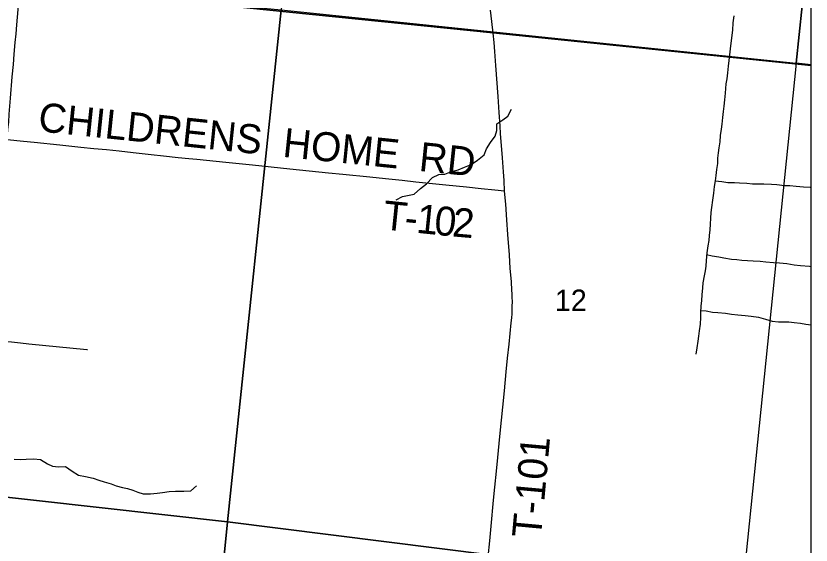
# Model space of a CAD drawing. Extents: x 0 to 1067, y 0 to 440.
# Drawn here: x 803.284 to 804.84, y 352.266 to 353.302 of the extents above; entities that cross this region are included whole.
import ezdxf

# ---------------------------------------------------------------- set-up
doc = ezdxf.new("R2010")
doc.units = 0
for name, color, linetype in [('GM_X_City_Street', 7, 'Continuous'), ('GM_X_Minor_River', 7, 'Continuous'), ('GM_X_Section', 7, 'Continuous'), ('GM_X_Section_Text', 7, 'Continuous'), ('GM_X_Township_Road', 7, 'Continuous'), ('GM_X_Township_Road_Text', 7, 'Continuous'), ('GM_X_US_Shield', 7, 'Continuous')]:
    doc.layers.add(name, color=color, linetype=linetype)

msp = doc.modelspace()

# ---------------------------------------------------------------- linework, layer by layer
at = {"layer": 'GM_X_City_Street'}
msp.add_lwpolyline([(803.254, 352.6093), (803.2546, 352.6163), (803.2565, 352.6361), (803.2583, 352.6522), (803.2589, 352.659), (803.2593, 352.6608), (803.2598, 352.6619), (803.2605, 352.6629), (803.2615, 352.6637), (803.2632, 352.6645), (803.265, 352.6647), (803.2755, 352.6637), (803.2935, 352.6618), (803.3095, 352.6601), (803.4231, 352.6488), (803.4243, 352.6487)], dxfattribs=at)
at = {"layer": 'GM_X_Minor_River'}
for points in [[(804.689, 353.302), (804.687, 353.2884), (804.6865, 353.274), (804.6853, 353.2641), (804.6837, 353.2528), (804.6825, 353.2433), (804.6812, 353.2316), (804.678, 353.2035), (804.6767, 353.1907), (804.6751, 353.1789), (804.6735, 353.1691), (804.6719, 353.1509), (804.6706, 353.1376), (804.6694, 353.1251), (804.6682, 353.1149), (804.6669, 353.1031), (804.6653, 353.0899), (804.6641, 353.08), (804.6621, 353.0675), (804.6613, 353.0554), (804.6596, 353.0437), (804.6584, 353.0342), (804.6572, 353.0236), (804.6567, 353.013), (804.6551, 353.0012), (804.6539, 352.9895), (804.6523, 352.9793), (804.6507, 352.9683), (804.6491, 352.9547), (804.6471, 352.9414), (804.6451, 352.927), (804.6442, 352.9172), (804.6434, 352.9062), (804.6425, 352.894), (804.6417, 352.8834), (804.6405, 352.8721), (804.64, 352.8626), (804.6384, 352.852), (804.636, 352.8384), (804.6348, 352.8232), (804.6343, 352.8122), (804.6331, 352.8027), (804.6311, 352.7929), (804.6283, 352.7797), (804.6275, 352.7694), (804.6266, 352.7558), (804.6254, 352.7448), (804.6246, 352.7338), (804.6237, 352.7213), (804.6236, 352.7114), (804.6231, 352.6986), (804.6211, 352.6857), (804.6199, 352.6754), (804.6183, 352.6656), (804.6167, 352.6523), (804.6147, 352.6399)], [(804.0281, 352.9422), (804.0407, 352.9486), (804.0536, 352.9511), (804.0634, 352.953), (804.0756, 352.9639), (804.0878, 352.9732), (804.0992, 352.9857), (804.1118, 352.9916), (804.1235, 352.9923), (804.1364, 352.9975), (804.1493, 353.0008), (804.1622, 353.006), (804.1747, 353.0112), (804.1873, 353.0198), (804.2002, 353.03), (804.2053, 353.0417), (804.2126, 353.0541), (804.2217, 353.0662), (804.2249, 353.0779), (804.225, 353.0908), (804.2368, 353.0987), (804.247, 353.1058), (804.2536, 353.1194)], [(804.6523, 352.9792), (804.6652, 352.9777), (804.6773, 352.976), (804.6905, 352.9756), (804.7003, 352.9751), (804.7147, 352.9746), (804.7253, 352.9734), (804.7476, 352.9732), (804.7627, 352.9727), (804.7733, 352.9718), (804.7884, 352.9702), (804.7983, 352.9697), (804.8111, 352.9685), (804.8255, 352.9676), (804.838, 352.9664), (804.8401, 352.966)], [(804.6357, 352.8347), (804.6466, 352.8326), (804.6594, 352.8306), (804.6692, 352.8286), (804.6843, 352.8258), (804.6949, 352.825), (804.7047, 352.8238), (804.7157, 352.8233), (804.7271, 352.8224), (804.7407, 352.8216), (804.7516, 352.8203), (804.7668, 352.8195), (804.7781, 352.8186), (804.7928, 352.8173), (804.8072, 352.8149), (804.8197, 352.8137), (804.8367, 352.812), (804.8401, 352.8113)], [(804.624, 352.7252), (804.6351, 352.7246), (804.6472, 352.7222), (804.6578, 352.7214), (804.6729, 352.7198), (804.6842, 352.7181), (804.6967, 352.7169), (804.7114, 352.7153), (804.7231, 352.714), (804.7371, 352.7124), (804.7507, 352.7081), (804.7639, 352.7046), (804.7764, 352.7033), (804.7866, 352.7029), (804.7964, 352.7032), (804.807, 352.7016), (804.8195, 352.7003), (804.8297, 352.6987), (804.8401, 352.6974)], [(803.2805, 352.4344), (803.2938, 352.4339), (803.304, 352.4346), (803.3184, 352.4348), (803.3324, 352.4336), (803.3459, 352.4255), (803.3557, 352.4209), (803.3674, 352.4193), (803.3811, 352.4199), (803.3942, 352.4111), (803.4066, 352.4031), (803.4206, 352.4003), (803.4353, 352.3971)], [(803.4353, 352.3971), (803.4463, 352.3933), (803.4568, 352.3898), (803.4708, 352.3859), (803.4806, 352.382), (803.4927, 352.3789), (803.5025, 352.3769), (803.5127, 352.3734), (803.5225, 352.3699), (803.5331, 352.3664), (803.5478, 352.3663), (803.5607, 352.3677), (803.5709, 352.3692), (803.5838, 352.3709), (803.5967, 352.372), (803.6129, 352.3715), (803.6266, 352.3721), (803.6376, 352.3819)]]:
    msp.add_lwpolyline(points, dxfattribs=at)
at = {"layer": 'GM_X_Section'}
for points in [[(803.8031, 353.3139), (803.6983, 352.312), (802.6931, 352.4236), (802.7829, 353.4125)], [(804.8106, 353.2091), (804.7094, 352.2121), (804.2114, 352.247), (803.6983, 352.312), (803.8031, 353.3139)], [(802.6931, 352.4236), (803.6983, 352.312), (803.5984, 351.3051), (802.5998, 351.3996)], [(803.6983, 352.312), (804.2114, 352.247), (804.7094, 352.2121), (804.6132, 351.2048), (803.5984, 351.3051)]]:
    msp.add_lwpolyline(points, close=True, dxfattribs=at)
at = {"layer": 'GM_X_Township_Road'}
for points in [[(803.2927, 353.3636), (804.2178, 353.2689), (804.8401, 353.205), (804.8401, 357.6021)], [(799.4572, 350.8021), (804.8401, 350.8021), (804.8401, 353.205), (804.2178, 353.2689), (803.2927, 353.3636)], [(803.2844, 353.2671), (803.2858, 353.2842), (803.2886, 353.3145), (803.2918, 353.3491), (803.293, 353.3631)], [(804.218, 353.2684), (804.2157, 353.2907), (804.2131, 353.3129)], [(803.2669, 353.0592), (803.2687, 353.0793), (803.2701, 353.0942), (803.2713, 353.1096), (803.2738, 353.1412), (803.2772, 353.1827), (803.2793, 353.2068), (803.2811, 353.2272), (803.283, 353.2501), (803.2844, 353.2671)], [(804.2404, 352.959), (804.2396, 352.9798), (804.2384, 352.9965), (804.2363, 353.0238), (804.2338, 353.056), (804.2327, 353.0708), (804.2316, 353.087), (804.23, 353.113), (804.2278, 353.144), (804.2235, 353.2047), (804.2215, 353.232), (804.2199, 353.2499), (804.218, 353.2684)], [(803.4864, 353.0373), (803.4617, 353.0396), (803.4364, 353.042), (803.4111, 353.0446), (803.3704, 353.0488), (803.3198, 353.0538), (803.2988, 353.0559), (803.2669, 353.0592)], [(804.2404, 352.959), (804.2215, 352.9609), (804.1945, 352.9636), (804.1659, 352.9666), (804.1256, 352.9708), (804.0931, 352.9742), (804.0665, 352.9768), (804.0399, 352.9795), (804.0072, 352.9828), (803.9769, 352.986), (803.9237, 352.9914), (803.8959, 352.9942), (803.8205, 353.0021), (803.747, 353.0096), (803.695, 353.0149), (803.6382, 353.0206), (803.6227, 353.0221), (803.6017, 353.0243), (803.5733, 353.0274), (803.5486, 353.0301), (803.5138, 353.0341), (803.4864, 353.0373)], [(804.2211, 352.3797), (804.2243, 352.4106), (804.2271, 352.4373), (804.2312, 352.4787), (804.2402, 352.5683), (804.2437, 352.6054), (804.2462, 352.6319), (804.2491, 352.6597), (804.2512, 352.6801), (804.2534, 352.7012), (804.2544, 352.7107), (804.255, 352.7185), (804.2551, 352.7239), (804.2555, 352.7338), (804.2556, 352.7421), (804.2554, 352.7517), (804.2549, 352.7584), (804.2545, 352.7645), (804.2536, 352.7819), (804.2516, 352.8078), (804.2497, 352.8344), (804.247, 352.8739), (804.245, 352.9027), (804.2427, 352.9336), (804.2404, 352.959)], [(804.2036, 352.1965), (804.2046, 352.2062), (804.2083, 352.2433), (804.2114, 352.2746), (804.2141, 352.3033), (804.2188, 352.3542), (804.2211, 352.3797)]]:
    msp.add_lwpolyline(points, dxfattribs=at)
at = {"layer": 'GM_X_US_Shield'}
for points in [[(804.8401, 353.4905), (804.8401, 354.2229), (803.9043, 354.3108), (803.8031, 353.3139), (804.8106, 353.2091)], [(804.8401, 353.2061), (804.8401, 353.4905), (804.8106, 353.2091)], [(804.8401, 352.1981), (804.8401, 353.2061), (804.8106, 353.2091), (804.7094, 352.2121)]]:
    msp.add_lwpolyline(points, close=True, dxfattribs=at)

# ---------------------------------------------------------------- texts
at = {"layer": 'GM_X_Section_Text'}
msp.add_text('12', height=0.04186, rotation=0, dxfattribs=at).set_placement((804.3389, 352.7244))
at = {"layer": 'GM_X_Township_Road_Text'}
for s, height, rotation, p in [('CHILDRENS', 0.05682, 354.0467, (803.3262, 353.0763)), ('HOME', 0.05682, 354.1511, (803.8047, 353.0262)), ('RD', 0.05682, 354.0932, (804.0712, 352.9987)), ('T', 0.0568, 354.1657, (804.0006, 352.8843)), ('1', 0.0568, 354.2111, (804.0661, 352.8776)), ('0', 0.0568, 354.3493, (804.1011, 352.874)), ('2', 0.0568, 354.9987, (804.1366, 352.8705)), ('-', 0.0568, 354.1791, (804.0429, 352.8799)), ('T-101', 0.05682, 84.733, (804.3113, 352.2787))]:
    msp.add_text(s, height=height, rotation=rotation, dxfattribs=at).set_placement(p)

doc.saveas('drawing.dxf')
